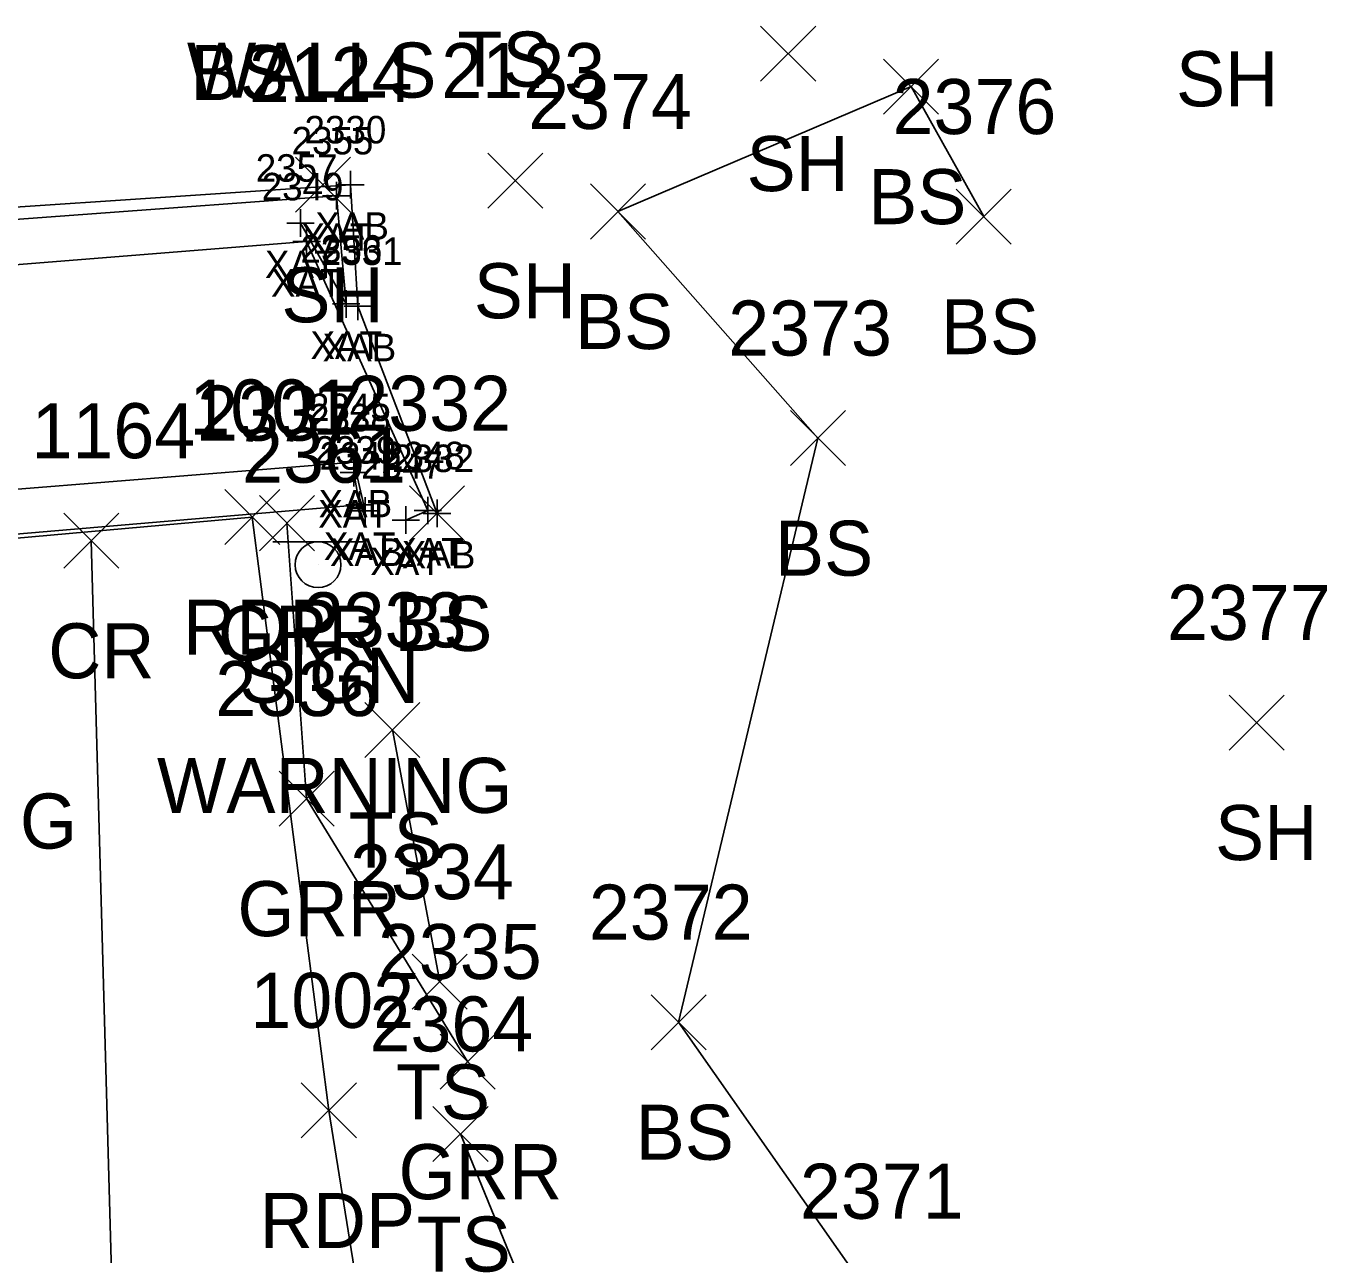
# Model space of a CAD drawing. Extents: x 1609623 to 1616187, y 756677 to 762826.
# Drawn here: x 1610612.97 to 1610660.25, y 761795.3 to 761839.97 of the extents above; entities that cross this region are included whole.
import ezdxf

# ---------------------------------------------------------------- set-up
doc = ezdxf.new("R2010")
doc.units = 0
for name, color, linetype in [('B_A', 7, 'Continuous'), ('B_I', 7, 'Continuous'), ('B_TIC', 7, 'Continuous'), ('BSUBM', 7, 'Continuous'), ('L_A', 7, 'Continuous'), ('L_I', 7, 'Continuous'), ('L_TIC', 7, 'Continuous'), ('LELB', 7, 'Continuous'), ('P_A', 7, 'Continuous'), ('P_I', 7, 'Continuous'), ('P_TIC', 7, 'Continuous'), ('PET', 7, 'Continuous'), ('PRC', 7, 'Continuous'), ('R_A', 7, 'Continuous'), ('R_I', 7, 'Continuous'), ('R_TIC', 7, 'Continuous'), ('RGR', 7, 'Continuous'), ('S_A', 7, 'Continuous'), ('S_C', 7, 'Continuous'), ('S_I', 7, 'Continuous'), ('SSGN', 7, 'Continuous')]:
    doc.layers.add(name, color=color, linetype=linetype)

msp = doc.modelspace()

# ---------------------------------------------------------------- linework, layer by layer
at = {"layer": 'B_TIC'}
for p, q in [((1610624.767, 761834.198), (1610624.843, 761834.198)), ((1610624.254, 761833.799), (1610624.329, 761833.799)), ((1610622.952, 761832.806), (1610623.028, 761832.806)), ((1610623.172, 761832.129), (1610623.248, 761832.129)), ((1610624.608, 761829.863), (1610624.684, 761829.863)), ((1610625.032, 761829.78), (1610625.107, 761829.78)), ((1610624.886, 761824.108), (1610624.962, 761824.108)), ((1610624.89, 761823.734), (1610624.965, 761823.734)), ((1610625.095, 761822.559), (1610625.171, 761822.559)), ((1610625.301, 761822.342), (1610625.376, 761822.342)), ((1610627.579, 761822.355), (1610627.655, 761822.355)), ((1610627.912, 761822.254), (1610627.988, 761822.254)), ((1610626.781, 761822.012), (1610626.856, 761822.012))]:
    msp.add_line(p, q, dxfattribs=at)
for points in [[(1610624.764, 761833.698), (1610624.764, 761834.698)], [(1610624.25, 761833.299), (1610624.25, 761834.299)], [(1610624.264, 761834.198), (1610625.264, 761834.198)], [(1610623.75, 761833.799), (1610624.75, 761833.799)], [(1610622.949, 761832.306), (1610622.949, 761833.306)], [(1610622.449, 761832.806), (1610623.449, 761832.806)], [(1610623.169, 761831.629), (1610623.169, 761832.629)], [(1610622.669, 761832.129), (1610623.669, 761832.129)], [(1610624.605, 761829.363), (1610624.605, 761830.363)], [(1610625.028, 761829.28), (1610625.028, 761830.28)], [(1610624.105, 761829.863), (1610625.105, 761829.863)], [(1610624.528, 761829.78), (1610625.528, 761829.78)], [(1610624.883, 761823.608), (1610624.883, 761824.608)], [(1610624.383, 761824.108), (1610625.383, 761824.108)], [(1610624.886, 761823.234), (1610624.886, 761824.234)], [(1610624.386, 761823.734), (1610625.386, 761823.734)], [(1610625.092, 761822.059), (1610625.092, 761823.059)], [(1610625.297, 761821.842), (1610625.297, 761822.842)], [(1610627.576, 761821.855), (1610627.576, 761822.855)], [(1610627.909, 761821.754), (1610627.909, 761822.754)], [(1610624.592, 761822.559), (1610625.592, 761822.559)], [(1610624.797, 761822.342), (1610625.797, 761822.342)], [(1610626.777, 761821.512), (1610626.777, 761822.512)], [(1610627.076, 761822.355), (1610628.076, 761822.355)], [(1610627.409, 761822.254), (1610628.409, 761822.254)], [(1610626.277, 761822.012), (1610627.277, 761822.012)]]:
    msp.add_lwpolyline(points, dxfattribs=at)
at = {"layer": 'BSUBM'}
for points in [[(1610605.115, 761832.882), (1610624.764, 761834.198), (1610625.028, 761829.78), (1610627.909, 761822.254)], [(1610605.817, 761829.624), (1610606.047, 761831.137), (1610605.802, 761832.431), (1610624.25, 761833.799), (1610624.605, 761829.863), (1610622.949, 761832.806)], [(1610626.777, 761822.012), (1610627.576, 761822.355), (1610623.169, 761832.129), (1610606.35, 761830.794), (1610604.858, 761820.882)], [(1610608.499, 761820.987), (1610606.886, 761820.914), (1610606.777, 761822.663), (1610624.883, 761824.108), (1610625.297, 761822.342)], [(1610624.886, 761823.734), (1610625.092, 761822.559), (1610607.05, 761821.029), (1610606.982, 761822.298)]]:
    msp.add_lwpolyline(points, dxfattribs=at)
at = {"layer": 'L_TIC'}
for points in [[(1610639.671, 761837.965), (1610641.671, 761839.965)], [(1610641.671, 761837.965), (1610639.671, 761839.965)], [(1610644.138, 761836.763), (1610646.138, 761838.763)], [(1610646.138, 761836.763), (1610644.138, 761838.763)], [(1610622.764, 761833.198), (1610624.764, 761835.198)], [(1610624.764, 761833.198), (1610622.764, 761835.198)], [(1610629.756, 761833.344), (1610631.756, 761835.344)], [(1610631.756, 761833.344), (1610629.756, 761835.344)], [(1610633.482, 761832.224), (1610635.482, 761834.224)], [(1610635.482, 761832.224), (1610633.482, 761834.224)], [(1610646.78, 761832.038), (1610648.78, 761834.038)], [(1610648.78, 761832.038), (1610646.78, 761834.038)], [(1610640.752, 761823.988), (1610642.752, 761825.988)], [(1610642.752, 761823.988), (1610640.752, 761825.988)], [(1610626.909, 761821.254), (1610628.909, 761823.254)], [(1610628.909, 761821.254), (1610626.909, 761823.254)], [(1610656.699, 761813.652), (1610658.699, 761815.652)], [(1610658.699, 761813.652), (1610656.699, 761815.652)], [(1610625.287, 761813.382), (1610627.287, 761815.382)], [(1610627.287, 761813.382), (1610625.287, 761815.382)], [(1610627.006, 761804.23), (1610629.006, 761806.23)], [(1610629.006, 761804.23), (1610627.006, 761806.23)], [(1610635.689, 761802.761), (1610637.689, 761804.761)], [(1610637.689, 761802.761), (1610635.689, 761804.761)], [(1610627.762, 761798.698), (1610629.762, 761800.698)], [(1610629.762, 761798.698), (1610627.762, 761800.698)]]:
    msp.add_lwpolyline(points, dxfattribs=at)
at = {"layer": 'LELB'}
for points in [[(1610646.043, 761735.812), (1610647.663, 761756.502), (1610645.199, 761774.687), (1610643.791, 761793.616), (1610636.689, 761803.761), (1610641.752, 761824.988), (1610634.482, 761833.224), (1610645.138, 761837.763), (1610647.78, 761833.038)], [(1610626.287, 761814.382), (1610628.006, 761805.23)], [(1610628.762, 761799.698), (1610634.58, 761785.483), (1610634.223, 761755.426), (1610632.185, 761740.564), (1610646.043, 761735.812)]]:
    msp.add_lwpolyline(points, dxfattribs=at)
at = {"layer": 'P_TIC'}
for points in [[(1610620.192, 761821.118), (1610622.192, 761823.118)], [(1610622.192, 761821.118), (1610620.192, 761823.118)], [(1610614.344, 761820.258), (1610616.344, 761822.258)], [(1610616.344, 761820.258), (1610614.344, 761822.258)], [(1610622.976, 761799.555), (1610624.976, 761801.555)], [(1610624.976, 761799.555), (1610622.976, 761801.555)]]:
    msp.add_lwpolyline(points, dxfattribs=at)
at = {"layer": 'PET'}
msp.add_lwpolyline([(1610609.916, 761821.115), (1610621.192, 761822.118), (1610623.976, 761800.555), (1610628.71, 761771.075), (1610628.457, 761733.135), (1610630.542, 761698.266), (1610630.634, 761648.448), (1610632.483, 761602.637)], dxfattribs=at)
at = {"layer": 'PRC'}
msp.add_lwpolyline([(1610615.344, 761821.258), (1610616.764, 761769.945), (1610617.486, 761726.015), (1610618.266, 761675.989), (1610618.81, 761645.854), (1610620.706, 761596.252), (1610622.201, 761543.733), (1610623.768, 761494.009), (1610624.803, 761445.349), (1610626.12, 761399.371), (1610627.458, 761348.429), (1610629.428, 761292.428), (1610633.696, 761219.48)], dxfattribs=at)
at = {"layer": 'R_TIC'}
for points in [[(1610621.453, 761820.897), (1610623.453, 761822.897)], [(1610623.453, 761820.897), (1610621.453, 761822.897)], [(1610622.166, 761810.887), (1610624.166, 761812.887)], [(1610624.166, 761810.887), (1610622.166, 761812.887)], [(1610628.022, 761801.328), (1610630.022, 761803.328)], [(1610630.022, 761801.328), (1610628.022, 761803.328)]]:
    msp.add_lwpolyline(points, dxfattribs=at)
at = {"layer": 'RGR'}
msp.add_lwpolyline([(1610629.022, 761802.328), (1610623.166, 761811.887), (1610622.453, 761821.897)], dxfattribs=at)
at = {"layer": 'SSGN'}
for p, q in [((1610621.936, 761821.22), (1610625.269, 761821.22)), ((1610623.583, 761820.387), (1610623.583, 761820.387))]:
    msp.add_line(p, q, dxfattribs=at)
msp.add_circle((1610623.583, 761820.387), 0.833, dxfattribs=at)

# ---------------------------------------------------------------- texts
at = {"layer": 'B_A'}
for s, p in [('XAB', (1610623.484, 761832.198)), ('XAT', (1610622.955, 761831.799)), ('XAT', (1610621.654, 761830.806)), ('XAT', (1610621.874, 761830.129)), ('XAT', (1610623.309, 761827.863)), ('XAB', (1610623.749, 761827.78)), ('XAB', (1610623.603, 761822.108)), ('XAT', (1610623.591, 761821.734)), ('XAT', (1610623.796, 761820.559)), ('XAB', (1610624.018, 761820.342)), ('XAT', (1610626.28, 761820.355)), ('XAB', (1610626.629, 761820.254)), ('XAT', (1610625.482, 761820.012))]:
    msp.add_text(s, height=1, dxfattribs=at).set_placement(p)
at = {"layer": 'B_I'}
for s, p in [('2330', (1610623.091, 761835.698)), ('2355', (1610622.62, 761835.299)), ('2357', (1610621.319, 761834.306)), ('2349', (1610621.535, 761833.629)), ('2356', (1610622.947, 761831.363)), ('2331', (1610623.682, 761831.28)), ('2345', (1610623.253, 761825.608)), ('2338', (1610623.256, 761825.234)), ('2339', (1610623.458, 761824.059)), ('2346', (1610623.64, 761823.842)), ('2347', (1610625.148, 761823.512)), ('2348', (1610625.946, 761823.855)), ('2332', (1610626.279, 761823.754))]:
    msp.add_text(s, height=1, dxfattribs=at).set_placement(p)
at = {"layer": 'L_A'}
for s, p in [('TS', (1610628.652, 761837.762)), ('WALLS', (1610618.818, 761837.364)), ('BS', (1610618.938, 761837.272)), ('SH', (1610654.766, 761837.048)), ('SH', (1610639.159, 761833.965)), ('BS', (1610643.579, 761832.763)), ('SH', (1610622.252, 761829.198)), ('SH', (1610629.245, 761829.344)), ('BS', (1610632.923, 761828.224)), ('BS', (1610646.221, 761828.038)), ('BS', (1610640.193, 761819.988)), ('BS', (1610626.35, 761817.254)), ('TS', (1610624.697, 761809.382)), ('SH', (1610656.187, 761809.652)), ('TS', (1610626.416, 761800.23)), ('BS', (1610635.13, 761798.761)), ('TS', (1610627.172, 761794.698))]:
    msp.add_text(s, height=2, dxfattribs=at).set_placement(p)
at = {"layer": 'L_I'}
for s, p in [('2124', (1610621.071, 761837.198)), ('2123', (1610628.064, 761837.344)), ('2374', (1610631.223, 761836.224)), ('2376', (1610644.465, 761836.038)), ('2373', (1610638.493, 761827.988)), ('2332', (1610624.649, 761825.254)), ('2333', (1610623.027, 761817.382)), ('2377', (1610654.439, 761817.652)), ('2334', (1610624.747, 761808.23)), ('2372', (1610633.43, 761806.761)), ('2364', (1610625.455, 761802.698)), ('2371', (1610641.098, 761796.616))]:
    msp.add_text(s, height=2, dxfattribs=at).set_placement(p)
at = {"layer": 'P_A'}
for s, p in [('RDP', (1610618.68, 761817.118)), ('CR', (1610613.777, 761816.258)), ('RDP', (1610621.464, 761795.555))]:
    msp.add_text(s, height=2, dxfattribs=at).set_placement(p)
at = {"layer": 'P_I'}
for s, p in [('1001', (1610618.909, 761825.118)), ('1164', (1610613.17, 761824.258)), ('1002', (1610621.125, 761803.555))]:
    msp.add_text(s, height=2, dxfattribs=at).set_placement(p)
at = {"layer": 'R_A'}
for p in [(1610619.941, 761816.897), (1610620.654, 761806.887), (1610626.51, 761797.328)]:
    msp.add_text('GRR', height=2, dxfattribs=at).set_placement(p)
at = {"layer": 'R_I'}
for s, p in [('2337', (1610619.193, 761824.897)), ('2336', (1610619.851, 761814.887)), ('2335', (1610625.762, 761805.328))]:
    msp.add_text(s, height=2, dxfattribs=at).set_placement(p)
at = {"layer": 'S_A'}
msp.add_text('SIGN', height=2, dxfattribs=at).set_placement((1610620.721, 761815.367))
at = {"layer": 'S_C'}
for p in [(1610617.729, 761811.367), (1610601.902, 761810.071)]:
    msp.add_text('WARNING', height=2, dxfattribs=at).set_placement(p)
at = {"layer": 'S_I'}
msp.add_text('2361', height=2, dxfattribs=at).set_placement((1610620.823, 761823.367))

doc.saveas('drawing.dxf')
